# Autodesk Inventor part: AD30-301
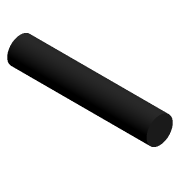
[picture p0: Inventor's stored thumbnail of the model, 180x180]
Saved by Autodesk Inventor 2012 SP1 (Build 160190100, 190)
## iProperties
Shininess: 0.0
Length Units: 11269
Angle Units: 11279
Time Units: 11290
Mass Units: 11283
Length Display Precision: 3
Angle Display Precision: 2
Compacted: True
Created: 2000-09
Part Number: AD30-301
Description: HANDLE BAR
Document SubType Name: Modeling
Designer: Ron
Density: 1 g/cm^3
Material: Default
Density: 0.0
Volumn: 0.0
Area: 0.0
PropertySet Name: Model Information
Control State: 0
Master: False
Checked Out: False
Author: Ron
Revision Number: A
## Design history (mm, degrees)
node "Revolution1" dims "d2" = 90 deg
  sketch "Sketch1"
    geometry: L1 (135, 12.7)-(0, 12.7); L2 (0, 12.7)-(0, 0); L3 (0, 0)-(135, 0); L4 (135, 0)-(135, 12.7); 1 further point
    constraints: 8 end point, 2 parallel, 1 coincident, 1 horizontal, 1 perpendicular
    dimensions: "d27" = 135 distance between parallel lines of L4 L2; "d35" = 25.4 diameter of L1 L3
workaxis "Work Axis1"
node "Hole3" dims "d28" = 6.4008, "d29" = 4, "d30" = 2, "d31" = 60 deg, "d32" = 25.4, "d33" = 118 deg, "d34" = 19.05
  sketch "Sketch7"
    geometry: C1 r 12.7 at (0, 0) reference; 1 further point
    constraints: 1 coincident
body "Solid1"
